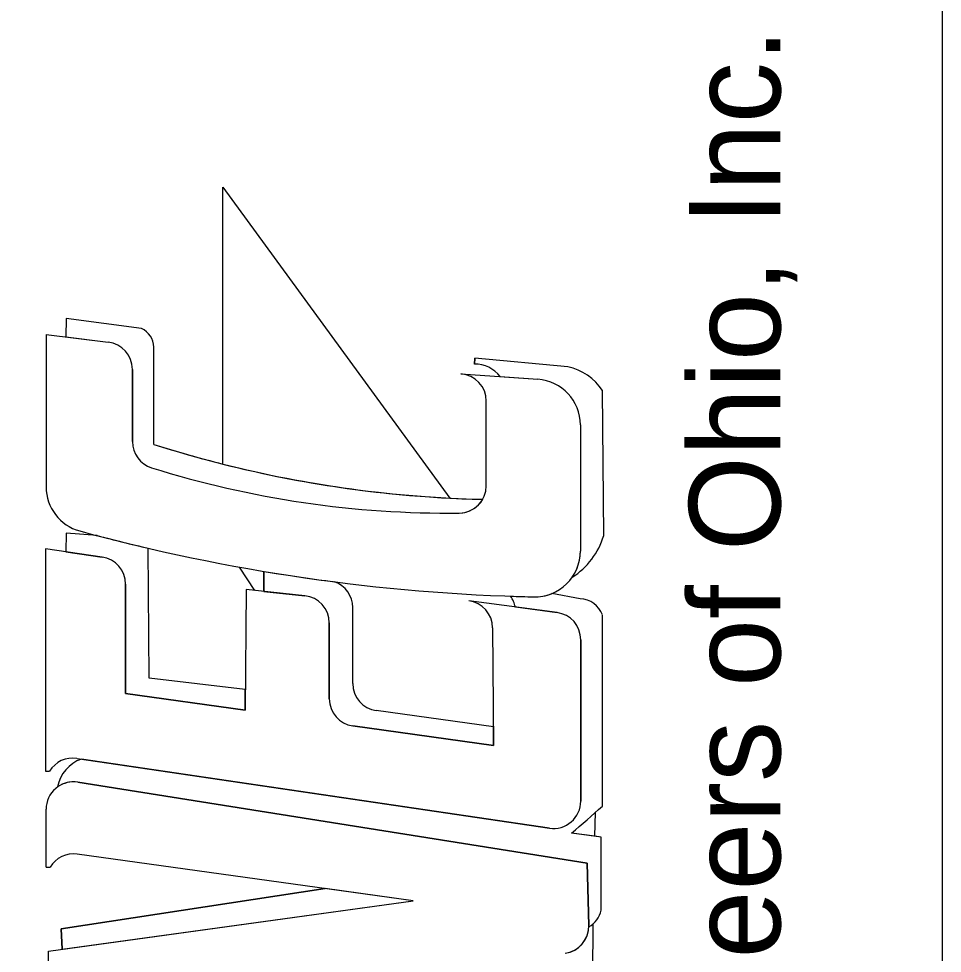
# Model space of a CAD drawing. Extents: x 0 to 34, y 0 to 22.
# Drawn here: x 32.735 to 33.5, y 18.534 to 19.308 of the extents above; entities that cross this region are included whole.
import ezdxf

# ---------------------------------------------------------------- set-up
doc = ezdxf.new("R2010")
doc.units = 0
doc.layers.add('SH_Border', color=7, linetype='Continuous')

msp = doc.modelspace()

# ---------------------------------------------------------------- linework, layer by layer
at = {"layer": 'SH_Border'}
for p, q in [((32.90393, 18.93905), (32.90403, 19.16824)), ((32.90393, 18.93905), (32.90403, 19.16824)), ((32.90393, 18.93905), (32.90403, 19.16824)), ((32.90403, 19.16824), (33.09206, 18.91081)), ((32.90403, 19.16824), (33.09206, 18.91081)), ((32.90403, 19.16824), (33.09206, 18.91081)), ((32.77413, 19.05948), (32.77403, 19.04425)), ((32.77413, 19.05948), (32.77403, 19.04425)), ((32.77413, 19.05948), (32.77403, 19.04425)), ((32.83673, 19.05126), (32.77413, 19.05948)), ((32.83673, 19.05126), (32.77413, 19.05948)), ((32.83673, 19.05126), (32.77413, 19.05948)), ((32.75763, 19.04627), (32.80918, 19.03992)), ((32.75763, 19.04627), (32.75763, 18.92012)), ((32.75763, 19.04627), (32.80918, 19.03992)), ((32.75763, 19.04627), (32.75763, 18.92012)), ((32.75763, 19.04627), (32.80918, 19.03992)), ((32.75763, 19.04627), (32.75763, 18.92012)), ((32.84699, 18.95529), (32.84699, 19.03586)), ((32.84699, 18.95529), (32.84699, 19.03586)), ((32.84699, 18.95529), (32.84699, 19.03586)), ((33.11244, 19.0218), (33.11277, 19.02662)), ((33.11244, 19.0218), (33.11277, 19.02662)), ((33.11244, 19.0218), (33.11277, 19.02662)), ((33.18974, 19.01943), (33.11277, 19.02662)), ((33.18974, 19.01943), (33.11277, 19.02662)), ((33.18974, 19.01943), (33.11277, 19.02662)), ((32.82909, 18.95759), (32.82909, 19.0174)), ((32.82909, 18.95759), (32.82909, 19.0174)), ((32.82909, 18.95759), (32.82909, 19.0174)), ((33.10119, 19.01372), (33.16501, 19.00922)), ((33.10119, 19.01372), (33.16501, 19.00922)), ((33.10119, 19.01372), (33.16501, 19.00922)), ((33.21949, 18.87978), (33.21847, 18.99992)), ((33.21949, 18.87978), (33.21847, 18.99992)), ((33.21949, 18.87978), (33.21847, 18.99992)), ((33.12228, 18.92112), (33.12228, 18.99109)), ((33.12228, 18.92112), (33.12228, 18.99109)), ((33.12228, 18.92112), (33.12228, 18.99109)), ((33.20016, 18.9715), (33.20016, 18.86687)), ((33.20016, 18.9715), (33.20016, 18.86687)), ((33.20016, 18.9715), (33.20016, 18.86687)), ((32.77413, 18.88183), (32.77397, 18.86631)), ((32.77413, 18.88183), (32.77397, 18.86631)), ((32.77413, 18.88183), (32.77397, 18.86631)), ((32.80005, 18.87975), (32.77413, 18.88183)), ((32.80005, 18.87975), (32.77413, 18.88183)), ((32.80005, 18.87975), (32.77413, 18.88183)), ((32.80404, 18.86201), (32.75723, 18.8687)), ((32.75723, 18.8687), (32.75723, 18.68468)), ((32.80404, 18.86201), (32.75723, 18.8687)), ((32.75723, 18.8687), (32.75723, 18.68468)), ((32.80404, 18.86201), (32.75723, 18.8687)), ((32.75723, 18.8687), (32.75723, 18.68468)), ((32.84289, 18.76169), (32.8423, 18.86932)), ((32.84289, 18.76169), (32.8423, 18.86932)), ((32.84289, 18.76169), (32.8423, 18.86932)), ((32.93051, 18.83436), (32.91783, 18.85373)), ((32.93051, 18.83436), (32.91783, 18.85373)), ((32.93051, 18.83436), (32.91783, 18.85373)), ((32.93788, 18.83359), (32.93813, 18.8502)), ((32.93788, 18.83359), (32.93813, 18.8502)), ((32.93788, 18.83359), (32.93813, 18.8502)), ((32.82351, 18.74898), (32.82351, 18.83955)), ((32.82351, 18.74898), (32.82351, 18.83955)), ((32.82351, 18.74898), (32.82351, 18.83955)), ((32.92336, 18.83511), (32.9225, 18.73519)), ((32.92336, 18.83511), (32.9225, 18.73519)), ((32.92336, 18.83511), (32.9225, 18.73519)), ((32.9719, 18.83004), (32.92336, 18.83511)), ((32.9719, 18.83004), (32.92336, 18.83511)), ((32.9719, 18.83004), (32.92336, 18.83511)), ((33.18085, 18.81609), (33.10774, 18.82584)), ((33.18085, 18.81609), (33.10774, 18.82584)), ((33.18085, 18.81609), (33.10774, 18.82584)), ((33.2, 18.82741), (33.17648, 18.83179)), ((33.2, 18.82741), (33.17648, 18.83179)), ((33.2, 18.82741), (33.17648, 18.83179)), ((33.0116, 18.75739), (33.0116, 18.82019)), ((33.0116, 18.75739), (33.0116, 18.82019)), ((33.0116, 18.75739), (33.0116, 18.82019)), ((33.21847, 18.65593), (33.21847, 18.81406)), ((33.21847, 18.65593), (33.21847, 18.81406)), ((33.21847, 18.65593), (33.21847, 18.81406)), ((32.99223, 18.74468), (32.99223, 18.80747)), ((32.99223, 18.74468), (32.99223, 18.80747)), ((32.99223, 18.74468), (32.99223, 18.80747)), ((33.12742, 18.80354), (33.12823, 18.70591)), ((33.12742, 18.80354), (33.12823, 18.70591)), ((33.12742, 18.80354), (33.12823, 18.70591)), ((33.20054, 18.66001), (33.20054, 18.7936)), ((33.20054, 18.66001), (33.20054, 18.7936)), ((33.20054, 18.66001), (33.20054, 18.7936)), ((32.92265, 18.75244), (32.84289, 18.76169)), ((32.92265, 18.75244), (32.84289, 18.76169)), ((32.92265, 18.75244), (32.84289, 18.76169)), ((32.9225, 18.73519), (32.82351, 18.74898)), ((32.9225, 18.73519), (32.82351, 18.74898)), ((32.9225, 18.73519), (32.82351, 18.74898)), ((33.1281, 18.72135), (33.03114, 18.73492)), ((33.1281, 18.72135), (33.03114, 18.73492)), ((33.1281, 18.72135), (33.03114, 18.73492)), ((33.12823, 18.70591), (33.01177, 18.72221)), ((33.12823, 18.70591), (33.01177, 18.72221)), ((33.12823, 18.70591), (33.01177, 18.72221)), ((32.78324, 18.69539), (33.17453, 18.63757)), ((32.78324, 18.69539), (33.17453, 18.63757)), ((32.78324, 18.69539), (33.17453, 18.63757)), ((32.75723, 18.68468), (32.7605, 18.68468)), ((32.75723, 18.68468), (32.7605, 18.68468)), ((32.75723, 18.68468), (32.7605, 18.68468)), ((33.20574, 18.60856), (32.78391, 18.67561)), ((33.20574, 18.60856), (32.78391, 18.67561)), ((33.20574, 18.60856), (32.78391, 18.67561)), ((32.75766, 18.60527), (32.75766, 18.65321)), ((32.75766, 18.60527), (32.75766, 18.65321)), ((32.75766, 18.60527), (32.75766, 18.65321)), ((33.21224, 18.63091), (33.2126, 18.65058)), ((33.21224, 18.63091), (33.2126, 18.65058)), ((33.21224, 18.63091), (33.2126, 18.65058)), ((33.21744, 18.63026), (33.19281, 18.63334)), ((33.21744, 18.63026), (33.19281, 18.63334)), ((33.21744, 18.63026), (33.19281, 18.63334)), ((33.21744, 18.56967), (33.21744, 18.63026)), ((33.21744, 18.56967), (33.21744, 18.63026)), ((33.21744, 18.56967), (33.21744, 18.63026)), ((33.06167, 18.57756), (32.78345, 18.61601)), ((33.06167, 18.57756), (32.78345, 18.61601)), ((33.06167, 18.57756), (32.78345, 18.61601)), ((33.20709, 18.55706), (33.20574, 18.60856)), ((33.20709, 18.55706), (33.20574, 18.60856)), ((33.20709, 18.55706), (33.20574, 18.60856)), ((32.75766, 18.60527), (32.76093, 18.60527)), ((32.75766, 18.60527), (32.76093, 18.60527)), ((32.75766, 18.60527), (32.76093, 18.60527)), ((32.77003, 18.55427), (32.98868, 18.58765)), ((32.77003, 18.55427), (32.98868, 18.58765)), ((32.77003, 18.55427), (32.98868, 18.58765)), ((32.75958, 18.53571), (33.06167, 18.57756)), ((32.75958, 18.53571), (33.06167, 18.57756)), ((32.75958, 18.53571), (33.06167, 18.57756)), ((32.77099, 18.53729), (32.77003, 18.55427)), ((32.77099, 18.53729), (32.77003, 18.55427)), ((32.77099, 18.53729), (32.77003, 18.55427)), ((33.21018, 18.47319), (33.2109, 18.55855)), ((33.21018, 18.47319), (33.2109, 18.55855)), ((33.21018, 18.47319), (33.2109, 18.55855)), ((32.75958, 18.47525), (32.75958, 18.53571)), ((32.75958, 18.47525), (32.75958, 18.53571)), ((32.75958, 18.47525), (32.75958, 18.53571))]:
    msp.add_line(p, q, dxfattribs=at)
msp.add_lwpolyline([(2, 21.5), (33.5, 21.5), (33.5, 0.5), (2, 0.5)], close=True, dxfattribs=at)
for points in [[(32.83673, 19.05126), (32.77413, 19.05948), (32.77403, 19.04425), (32.80918, 19.03992)], [(32.83673, 19.05126), (32.77413, 19.05948), (32.77403, 19.04425), (32.80918, 19.03992)], [(32.83673, 19.05126), (32.77413, 19.05948), (32.77403, 19.04425), (32.80918, 19.03992)], [(32.84699, 18.95529), (32.84699, 19.03586)], [(32.84699, 18.95529), (32.84699, 19.03586)], [(32.84699, 18.95529), (32.84699, 19.03586)], [(33.18974, 19.01943), (33.11277, 19.02662), (33.11244, 19.0218)], [(33.18974, 19.01943), (33.11277, 19.02662), (33.11244, 19.0218)], [(33.18974, 19.01943), (33.11277, 19.02662), (33.11244, 19.0218)], [(32.82909, 19.0174), (32.82909, 18.95759)], [(32.82909, 19.0174), (32.82909, 18.95759)], [(32.82909, 19.0174), (32.82909, 18.95759)], [(33.13378, 19.01142), (33.16501, 19.00922)], [(33.13378, 19.01142), (33.16501, 19.00922)], [(33.13378, 19.01142), (33.16501, 19.00922)], [(33.21949, 18.87978), (33.21847, 18.99992)], [(33.21949, 18.87978), (33.21847, 18.99992)], [(33.21949, 18.87978), (33.21847, 18.99992)], [(33.20016, 18.9715), (33.20016, 18.86687)], [(33.20016, 18.9715), (33.20016, 18.86687)], [(33.20016, 18.9715), (33.20016, 18.86687)], [(32.80005, 18.87975), (32.77413, 18.88183), (32.77397, 18.86631), (32.80404, 18.86201)], [(32.80005, 18.87975), (32.77413, 18.88183), (32.77397, 18.86631), (32.80404, 18.86201)], [(32.80005, 18.87975), (32.77413, 18.88183), (32.77397, 18.86631), (32.80404, 18.86201)], [(32.82351, 18.83955), (32.82351, 18.74898), (32.9225, 18.73519), (32.92265, 18.75244), (32.84289, 18.76169), (32.8423, 18.86932)], [(32.82351, 18.83955), (32.82351, 18.74898), (32.9225, 18.73519), (32.92265, 18.75244), (32.84289, 18.76169), (32.8423, 18.86932)], [(32.82351, 18.83955), (32.82351, 18.74898), (32.9225, 18.73519), (32.92265, 18.75244), (32.84289, 18.76169), (32.8423, 18.86932)], [(32.93813, 18.8502), (32.93788, 18.83359), (32.9719, 18.83004)], [(32.93813, 18.8502), (32.93788, 18.83359), (32.9719, 18.83004)], [(32.93813, 18.8502), (32.93788, 18.83359), (32.9719, 18.83004)], [(33.2, 18.82741), (33.17648, 18.83179)], [(33.2, 18.82741), (33.17648, 18.83179)], [(33.2, 18.82741), (33.17648, 18.83179)], [(33.0116, 18.75739), (33.0116, 18.82019)], [(33.0116, 18.75739), (33.0116, 18.82019)], [(33.0116, 18.75739), (33.0116, 18.82019)], [(33.14632, 18.82069), (33.18085, 18.81609)], [(33.14632, 18.82069), (33.18085, 18.81609)], [(33.14632, 18.82069), (33.18085, 18.81609)], [(33.21847, 18.65593), (33.21847, 18.81406)], [(33.21847, 18.65593), (33.21847, 18.81406)], [(33.21847, 18.65593), (33.21847, 18.81406)], [(32.99223, 18.80747), (32.99223, 18.74468)], [(32.99223, 18.80747), (32.99223, 18.74468)], [(32.99223, 18.80747), (32.99223, 18.74468)], [(33.20054, 18.7936), (33.20054, 18.66001)], [(33.20054, 18.7936), (33.20054, 18.66001)], [(33.20054, 18.7936), (33.20054, 18.66001)], [(33.01177, 18.72221), (33.12823, 18.70591), (33.1281, 18.72135), (33.03114, 18.73492)], [(33.01177, 18.72221), (33.12823, 18.70591), (33.1281, 18.72135), (33.03114, 18.73492)], [(33.01177, 18.72221), (33.12823, 18.70591), (33.1281, 18.72135), (33.03114, 18.73492)], [(33.17453, 18.63757), (32.78692, 18.69484)], [(33.17453, 18.63757), (32.78692, 18.69484)], [(33.17453, 18.63757), (32.78692, 18.69484)], [(32.78391, 18.67561), (33.20574, 18.60856), (33.20709, 18.55706)], [(32.78391, 18.67561), (33.20574, 18.60856), (33.20709, 18.55706)], [(32.78391, 18.67561), (33.20574, 18.60856), (33.20709, 18.55706)], [(33.21744, 18.56967), (33.21744, 18.63026), (33.21224, 18.63091), (33.19281, 18.63334)], [(33.21744, 18.56967), (33.21744, 18.63026), (33.21224, 18.63091), (33.19281, 18.63334)], [(33.21744, 18.56967), (33.21744, 18.63026), (33.21224, 18.63091), (33.19281, 18.63334)], [(32.77099, 18.53729), (33.06167, 18.57756), (32.98868, 18.58765), (32.77003, 18.55427), (32.77099, 18.53729)], [(32.77099, 18.53729), (33.06167, 18.57756), (32.98868, 18.58765), (32.77003, 18.55427), (32.77099, 18.53729)], [(32.77099, 18.53729), (33.06167, 18.57756), (32.98868, 18.58765), (32.77003, 18.55427), (32.77099, 18.53729)], [(33.12557, 18.52524), (33.15391, 18.48279), (33.21018, 18.47319), (33.2109, 18.55855)], [(33.12557, 18.52524), (33.15391, 18.48279), (33.21018, 18.47319), (33.2109, 18.55855)], [(33.12557, 18.52524), (33.15391, 18.48279), (33.21018, 18.47319), (33.2109, 18.55855)]]:
    msp.add_lwpolyline(points, dxfattribs=at)
for centre, radius, start, end in [((32.82904, 19.03502), 0.01797, 2.67605, 64.66973), ((32.82904, 19.03502), 0.01797, 2.67605, 64.66973), ((32.82904, 19.03502), 0.01797, 2.67605, 64.66973), ((32.82904, 19.03502), 0.01797, 2.67605, 64.66973), ((32.82904, 19.03502), 0.01797, 2.67605, 64.66973), ((32.82904, 19.03502), 0.01797, 2.67605, 64.66973), ((32.8064, 19.0174), 0.02269, 0, 82.97897), ((32.8064, 19.0174), 0.02269, 0, 82.97897), ((32.8064, 19.0174), 0.02269, 0, 82.97897), ((32.8064, 19.0174), 0.02269, 0, 82.97897), ((32.8064, 19.0174), 0.02269, 0, 82.97897), ((32.8064, 19.0174), 0.02269, 0, 82.97897), ((33.11267, 18.99516), 0.02665, 37.62062, 90.50626), ((33.11267, 18.99516), 0.02665, 37.62062, 90.50626), ((33.11267, 18.99516), 0.02665, 37.62062, 90.50626), ((33.11267, 18.99516), 0.02665, 37.62062, 90.50626), ((33.11267, 18.99516), 0.02665, 37.62062, 90.50626), ((33.11267, 18.99516), 0.02665, 37.62062, 90.50626), ((33.18149, 18.97638), 0.04383, 32.4836, 79.16225), ((33.18149, 18.97638), 0.04383, 32.4836, 79.16225), ((33.18149, 18.97638), 0.04383, 32.4836, 79.16225), ((33.18149, 18.97638), 0.04383, 32.4836, 79.16225), ((33.18149, 18.97638), 0.04383, 32.4836, 79.16225), ((33.18149, 18.97638), 0.04383, 32.4836, 79.16225), ((33.09959, 18.99109), 0.02269, 0, 85.95966), ((33.09959, 18.99109), 0.02269, 0, 85.95966), ((33.09959, 18.99109), 0.02269, 0, 85.95966), ((33.16235, 18.9715), 0.03781, 0, 85.95966), ((33.16235, 18.9715), 0.03781, 0, 85.95966), ((33.16235, 18.9715), 0.03781, 0, 85.95966), ((33.16235, 18.9715), 0.03781, 0, 85.95966), ((33.16235, 18.9715), 0.03781, 0, 85.95966), ((33.16235, 18.9715), 0.03781, 0, 85.95966), ((32.85178, 18.95759), 0.02269, 180, 252.63321), ((32.85178, 18.95759), 0.02269, 180, 252.63321), ((32.85178, 18.95759), 0.02269, 180, 252.63321), ((32.85178, 18.95759), 0.02269, 180, 252.63321), ((32.85178, 18.95759), 0.02269, 180, 252.63321), ((32.85178, 18.95759), 0.02269, 180, 252.63321), ((33.14116, 19.87873), 0.96916, 252.33058, 268.70563), ((33.14116, 19.87873), 0.96916, 252.33058, 255.83129), ((33.14116, 19.87873), 0.96916, 252.33058, 268.70563), ((33.14116, 19.87873), 0.96916, 252.33058, 255.83129), ((33.14116, 19.87873), 0.96916, 252.33058, 268.70563), ((33.14116, 19.87873), 0.96916, 252.33058, 255.83129), ((33.0909, 19.72219), 0.82381, 252.63321, 270.62155), ((33.0909, 19.72219), 0.82381, 252.63321, 270.62155), ((33.0909, 19.72219), 0.82381, 252.63321, 270.62155), ((33.0909, 19.72219), 0.82381, 252.63321, 270.62155), ((33.0909, 19.72219), 0.82381, 252.63321, 270.62155), ((33.0909, 19.72219), 0.82381, 252.63321, 270.62155), ((33.14116, 19.87873), 0.96916, 255.83129, 268.70563), ((33.14116, 19.87873), 0.96916, 255.83129, 268.70563), ((33.14116, 19.87873), 0.96916, 255.83129, 268.70563), ((32.79544, 18.92012), 0.03781, 180, 254.79162), ((32.79544, 18.92012), 0.03781, 180, 254.79162), ((32.79544, 18.92012), 0.03781, 180, 254.79162), ((33.09959, 18.92112), 0.02269, 270.62155, 0), ((33.09959, 18.92112), 0.02269, 270.62155, 0), ((33.09959, 18.92112), 0.02269, 270.62155, 0), ((33.09959, 18.92112), 0.02269, 270.62155, 330.12404), ((33.09959, 18.92112), 0.02269, 270.62155, 330.12404), ((33.09959, 18.92112), 0.02269, 270.62155, 330.12404), ((33.1973, 20.39837), 1.56971, 254.79162, 268.69253), ((33.1973, 20.39837), 1.56971, 254.79162, 268.69253), ((33.1973, 20.39837), 1.56971, 254.79162, 268.69253), ((33.1973, 20.39837), 1.56971, 255.34062, 256.92894), ((33.1973, 20.39837), 1.56971, 255.34062, 256.92894), ((33.1973, 20.39837), 1.56971, 255.34062, 256.92894), ((33.16036, 18.89743), 0.06171, 302.39655, 343.37547), ((33.16036, 18.89743), 0.06171, 302.39655, 343.37547), ((33.16036, 18.89743), 0.06171, 302.39655, 343.37547), ((33.16036, 18.89743), 0.06171, 302.39655, 343.37547), ((33.16036, 18.89743), 0.06171, 302.39655, 343.37547), ((33.16036, 18.89743), 0.06171, 302.39655, 343.37547), ((33.16235, 18.86687), 0.03781, 268.69253, 0), ((33.16235, 18.86687), 0.03781, 268.69253, 0), ((33.16235, 18.86687), 0.03781, 268.69253, 0), ((33.16235, 18.86687), 0.03781, 325.27661, 0), ((33.16235, 18.86687), 0.03781, 325.27661, 0), ((33.16235, 18.86687), 0.03781, 325.27661, 0), ((32.80083, 18.83955), 0.02269, 0, 81.86464), ((32.80083, 18.83955), 0.02269, 0, 81.86464), ((32.80083, 18.83955), 0.02269, 0, 81.86464), ((32.80083, 18.83955), 0.02269, 0, 81.86464), ((32.80083, 18.83955), 0.02269, 0, 81.86464), ((32.80083, 18.83955), 0.02269, 0, 81.86464), ((33.1973, 20.39837), 1.56971, 260.49664, 262.65334), ((33.1973, 20.39837), 1.56971, 260.49664, 262.65334), ((33.1973, 20.39837), 1.56971, 260.49664, 262.65334), ((32.98891, 18.82019), 0.02269, 0, 70.25544), ((32.98891, 18.82019), 0.02269, 0, 70.25544), ((32.98891, 18.82019), 0.02269, 0, 70.25544), ((32.98891, 18.82019), 0.02269, 0, 70.25544), ((32.98891, 18.82019), 0.02269, 0, 70.25544), ((32.98891, 18.82019), 0.02269, 0, 70.25544), ((32.96954, 18.80747), 0.02269, 0, 84.03166), ((32.96954, 18.80747), 0.02269, 0, 84.03166), ((32.96954, 18.80747), 0.02269, 0, 84.03166), ((32.96954, 18.80747), 0.02269, 0, 84.03166), ((32.96954, 18.80747), 0.02269, 0, 84.03166), ((32.96954, 18.80747), 0.02269, 0, 84.03166), ((33.10474, 18.80335), 0.02269, 0.4732, 82.40046), ((33.10474, 18.80335), 0.02269, 0.4732, 82.40046), ((33.10474, 18.80335), 0.02269, 0.4732, 82.40046), ((33.12411, 18.81607), 0.02269, 11.76029, 36.6658), ((33.1973, 20.39837), 1.56971, 267.99237, 268.69253), ((33.12411, 18.81607), 0.02269, 11.76029, 36.6658), ((33.12411, 18.81607), 0.02269, 11.76029, 36.6658), ((33.1973, 20.39837), 1.56971, 267.99237, 268.69253), ((33.12411, 18.81607), 0.02269, 11.76029, 36.6658), ((33.12411, 18.81607), 0.02269, 11.76029, 36.6658), ((33.1973, 20.39837), 1.56971, 267.99237, 268.69253), ((33.12411, 18.81607), 0.02269, 11.76029, 36.6658), ((33.16235, 18.86687), 0.03781, 268.69253, 291.95024), ((33.16235, 18.86687), 0.03781, 268.69253, 291.95024), ((33.16235, 18.86687), 0.03781, 268.69253, 291.95024), ((33.19922, 18.80688), 0.02055, 20.45964, 87.82957), ((33.19922, 18.80688), 0.02055, 20.45964, 87.82957), ((33.19922, 18.80688), 0.02055, 20.45964, 87.82957), ((33.19922, 18.80688), 0.02055, 20.45964, 87.82957), ((33.19922, 18.80688), 0.02055, 20.45964, 87.82957), ((33.19922, 18.80688), 0.02055, 20.45964, 87.82957), ((33.17785, 18.7936), 0.02269, 0, 82.40046), ((33.17785, 18.7936), 0.02269, 0, 82.40046), ((33.17785, 18.7936), 0.02269, 0, 82.40046), ((33.17785, 18.7936), 0.02269, 0, 82.40046), ((33.17785, 18.7936), 0.02269, 0, 82.40046), ((33.17785, 18.7936), 0.02269, 0, 82.40046), ((33.03429, 18.75739), 0.02269, 180, 262.03311), ((33.03429, 18.75739), 0.02269, 180, 262.03311), ((33.03429, 18.75739), 0.02269, 180, 262.03311), ((33.03429, 18.75739), 0.02269, 180, 262.03311), ((33.03429, 18.75739), 0.02269, 180, 262.03311), ((33.03429, 18.75739), 0.02269, 180, 262.03311), ((33.01491, 18.74468), 0.02269, 180, 262.03311), ((33.01491, 18.74468), 0.02269, 180, 262.03311), ((33.01491, 18.74468), 0.02269, 180, 262.03311), ((33.01491, 18.74468), 0.02269, 180, 262.03311), ((33.01491, 18.74468), 0.02269, 180, 262.03311), ((33.01491, 18.74468), 0.02269, 180, 262.03311), ((32.77992, 18.67295), 0.02269, 81.59392, 148.85913), ((32.77992, 18.67295), 0.02269, 81.59392, 148.85913), ((32.77992, 18.67295), 0.02269, 81.59392, 148.85913), ((32.79692, 18.66632), 0.03022, 109.32309, 169.78308), ((32.79692, 18.66632), 0.03022, 109.32309, 169.78308), ((32.79692, 18.66632), 0.03022, 109.32309, 169.78308), ((32.79692, 18.66632), 0.03022, 109.32309, 169.78308), ((32.79692, 18.66632), 0.03022, 109.32309, 169.78308), ((32.79692, 18.66632), 0.03022, 109.32309, 169.78308), ((32.78034, 18.65321), 0.02269, 80.96848, 180), ((32.78034, 18.65321), 0.02269, 80.96848, 180), ((32.78034, 18.65321), 0.02269, 80.96848, 180), ((32.78034, 18.65321), 0.02269, 80.96848, 125.47349), ((32.78034, 18.65321), 0.02269, 80.96848, 125.47349), ((32.78034, 18.65321), 0.02269, 80.96848, 125.47349), ((33.17785, 18.66001), 0.02269, 261.59392, 0), ((33.17785, 18.66001), 0.02269, 261.59392, 0), ((33.17785, 18.66001), 0.02269, 261.59392, 0), ((33.17785, 18.66001), 0.02269, 261.59392, 0), ((33.17785, 18.66001), 0.02269, 261.59392, 0), ((33.17785, 18.66001), 0.02269, 261.59392, 0), ((32.7, 19.21884), 0.7653, 310.08662, 312.64602), ((32.7, 19.21884), 0.7653, 310.08662, 312.64602), ((32.7, 19.21884), 0.7653, 310.08662, 312.64602), ((32.7, 19.21884), 0.7653, 310.08662, 312.64602), ((32.7, 19.21884), 0.7653, 310.08662, 312.64602), ((32.7, 19.21884), 0.7653, 310.08662, 312.64602), ((32.78034, 18.59354), 0.02269, 82.13091, 148.85913), ((32.78034, 18.59354), 0.02269, 82.13091, 148.85913), ((32.78034, 18.59354), 0.02269, 82.13091, 148.85913), ((33.19685, 18.5743), 0.02111, 299.03105, 347.33987), ((33.19685, 18.5743), 0.02111, 299.03105, 347.33987), ((33.19685, 18.5743), 0.02111, 299.03105, 347.33987), ((33.19685, 18.5743), 0.02111, 299.03105, 347.33987), ((33.19685, 18.5743), 0.02111, 299.03105, 347.33987), ((33.19685, 18.5743), 0.02111, 299.03105, 347.33987), ((33.18441, 18.55646), 0.02269, 278.04089, 1.50643), ((33.18441, 18.55646), 0.02269, 278.04089, 1.50643), ((33.18441, 18.55646), 0.02269, 278.04089, 1.50643), ((33.18441, 18.55646), 0.02269, 278.04089, 358.43264), ((33.18441, 18.55646), 0.02269, 278.04089, 358.43264), ((33.18441, 18.55646), 0.02269, 278.04089, 358.43264), ((33.18441, 18.55646), 0.02269, 358.43264, 1.50643), ((33.18441, 18.55646), 0.02269, 358.43264, 1.50643), ((33.18441, 18.55646), 0.02269, 358.43264, 1.50643)]:
    msp.add_arc(centre, radius, start, end, dxfattribs=at)

# ---------------------------------------------------------------- texts
msp.add_text('Engineers of Ohio, Inc.', height=0.075625, rotation=90, dxfattribs=at).set_placement((33.36583, 18.27104))

doc.saveas('drawing.dxf')
